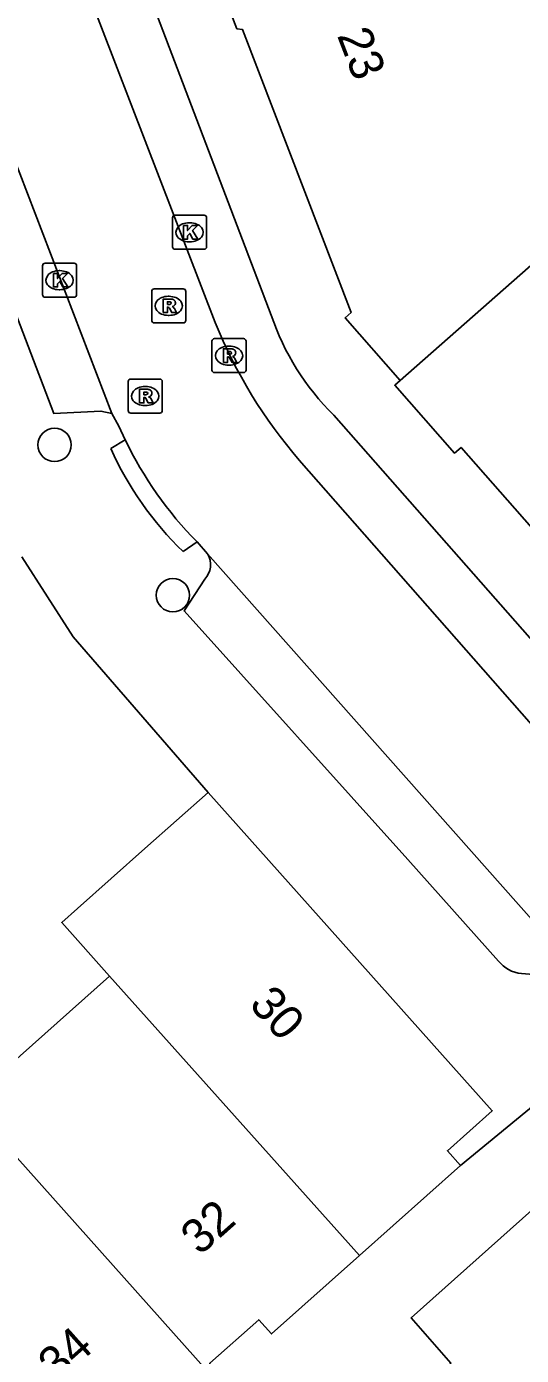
# Model space of a CAD drawing. Extents: x 159961 to 160856, y 382704 to 383353.
# Drawn here: x 160483.81 to 160498.33, y 383016.99 to 383056.02 of the extents above; entities that cross this region are included whole.
import ezdxf

# ---------------------------------------------------------------- set-up
doc = ezdxf.new("R2010")
doc.units = 0
for name, color, linetype in [('IMGEO_Boom', 7, 'Continuous'), ('IMGEO_Kolk', 7, 'Continuous'), ('IMGEO_Pand', 7, 'Continuous'), ('IMGEO_Pand_nummerreeks', 7, 'Continuous'), ('IMGEO_Rijbaan_lokaal_open', 7, 'Continuous'), ('IMGEO_Rioolput', 7, 'Continuous'), ('IMGEO_Voetpad_open', 7, 'Continuous')]:
    doc.layers.add(name, color=color, linetype=linetype)

msp = doc.modelspace()

# ---------------------------------------------------------------- linework, layer by layer
at = {"layer": 'IMGEO_Boom'}
for centre in [(160484.634, 383043.731), (160488.107, 383039.316)]:
    msp.add_circle(centre, 0.489, dxfattribs=at)
at = {"layer": 'IMGEO_Kolk'}
for p, q in [((160488.093, 383049.552), (160488.093, 383050.404)), ((160488.168, 383050.478), (160489.02, 383050.478)), ((160489.094, 383050.404), (160489.094, 383049.552)), ((160488.581, 383050.258), (160488.606, 383050.258)), ((160488.604, 383049.698), (160488.579, 383049.698)), ((160489.02, 383049.478), (160488.168, 383049.478)), ((160484.279, 383048.144), (160484.279, 383048.996)), ((160484.354, 383049.07), (160485.206, 383049.07)), ((160484.767, 383048.85), (160484.792, 383048.85)), ((160485.28, 383048.996), (160485.28, 383048.144)), ((160485.206, 383048.07), (160484.354, 383048.07)), ((160484.79, 383048.29), (160484.765, 383048.29))]:
    msp.add_line(p, q, dxfattribs=at)
for points in [[(160488.093, 383049.552), (160488.093, 383050.404)], [(160488.168, 383050.478), (160489.02, 383050.478)], [(160489.094, 383050.404), (160489.094, 383049.552)], [(160488.414, 383050.178), (160488.537, 383050.178), (160488.537, 383050.027), (160488.667, 383050.178), (160488.831, 383050.178), (160488.685, 383050.027), (160488.838, 383049.778), (160488.686, 383049.778), (160488.601, 383049.942), (160488.537, 383049.875), (160488.537, 383049.778), (160488.414, 383049.778), (160488.414, 383050.178)], [(160489.02, 383049.478), (160488.168, 383049.478)], [(160484.279, 383048.144), (160484.279, 383048.996)], [(160484.354, 383049.07), (160485.206, 383049.07)], [(160484.6, 383048.77), (160484.723, 383048.77), (160484.723, 383048.619), (160484.853, 383048.77), (160485.017, 383048.77), (160484.871, 383048.619), (160485.024, 383048.37), (160484.872, 383048.37), (160484.787, 383048.534), (160484.723, 383048.467), (160484.723, 383048.37), (160484.6, 383048.37), (160484.6, 383048.77)], [(160485.28, 383048.996), (160485.28, 383048.144)], [(160485.206, 383048.07), (160484.354, 383048.07)]]:
    msp.add_lwpolyline(points, dxfattribs=at)
for centre, start, end in [((160488.17, 383050.402), 91.552, 178.448), ((160488.17, 383050.402), 91.552, 178.448), ((160489.018, 383050.402), 1.552, 88.448), ((160489.018, 383050.402), 1.552, 88.448), ((160488.17, 383049.554), 181.552, 268.448), ((160488.17, 383049.554), 181.552, 268.448), ((160489.018, 383049.554), 271.552, 358.448), ((160489.018, 383049.554), 271.552, 358.448), ((160484.356, 383048.994), 91.552, 178.448), ((160484.356, 383048.994), 91.552, 178.448), ((160485.204, 383048.994), 1.552, 88.448), ((160485.204, 383048.994), 1.552, 88.448), ((160484.356, 383048.146), 181.552, 268.448), ((160484.356, 383048.146), 181.552, 268.448), ((160485.204, 383048.146), 271.552, 358.448), ((160485.204, 383048.146), 271.552, 358.448)]:
    msp.add_arc(centre, 0.0765, start, end, dxfattribs=at)
for centre, major_axis, ratio, start_param, end_param in [((160488.58, 383049.978), (-0.387, 0.002), 0.722429, 4.712389, 7.853982), ((160488.605, 383049.978), (-0.39, 0.002), 0.717154, 1.570796, 4.712389), ((160484.766, 383048.57), (-0.387, 0.002), 0.722429, 4.712389, 7.853982), ((160484.791, 383048.57), (-0.39, 0.002), 0.717154, 1.570796, 4.712389)]:
    msp.add_ellipse(centre, major_axis=major_axis, ratio=ratio, start_param=start_param, end_param=end_param, dxfattribs=at)
at = {"layer": 'IMGEO_Pand'}
for points in [[(160494.772, 383045.622), (160493.157, 383047.463), (160493.334, 383047.616), (160490.149, 383055.929), (160489.984, 383055.956), (160488.238, 383060.513), (160488.377, 383060.566), (160487.54, 383062.75), (160487.344, 383062.675), (160486.731, 383064.243)], [(160494.772, 383045.622), (160500, 383050.23), (160501.189, 383051.278), (160501.699, 383050.7), (160505.96, 383054.457)], [(160500.55, 383038.771), (160500.28, 383039.078), (160500.455, 383039.226), (160500, 383039.744), (160496.56, 383043.66), (160496.366, 383043.49), (160494.616, 383045.484), (160494.772, 383045.622)], [(160486.246, 383028.13), (160484.846, 383029.698), (160485.311, 383030.113), (160487.286, 383031.874), (160489.136, 383033.524)], [(160489.136, 383033.524), (160497.475, 383024.171), (160496.158, 383022.996), (160496.543, 383022.564)], [(160482.075, 383024.411), (160486.246, 383028.13)], [(160486.246, 383028.13), (160493.577, 383019.919)], [(160489.174, 383016.46), (160482.075, 383024.411)], [(160493.577, 383019.919), (160496.543, 383022.564)], [(160493.577, 383019.919), (160490.995, 383017.618), (160490.622, 383018.036), (160489.191, 383016.76), (160489.174, 383016.46)]]:
    msp.add_lwpolyline(points, dxfattribs=at)
at = {"layer": 'IMGEO_Rijbaan_lokaal_open'}
for points in [[(160489.35, 383047.33), (160483.958, 383061.336)], [(160486.314, 383044.65), (160480.452, 383059.937)], [(160486.707, 383043.878), (160486.52, 383044.285), (160486.314, 383044.65)], [(160503.746, 383030.245), (160503.457, 383030.012), (160491.815, 383043.282)], [(160489.125, 383040.531), (160488.815, 383040.881)], [(160489.125, 383040.531), (160500.697, 383027.462), (160500.334, 383027.185)]]:
    msp.add_lwpolyline(points, dxfattribs=at)
for centre, radius, start, end in [((160502.589, 383052.617), 14.256, 201.7703, 220.9078), ((160496.744, 383048.698), 11.134, 205.6505, 224.5923)]:
    msp.add_arc(centre, radius, start, end, dxfattribs=at)
at = {"layer": 'IMGEO_Rioolput'}
for p, q in [((160487.483, 383047.39), (160487.483, 383048.242)), ((160487.558, 383048.316), (160488.41, 383048.316)), ((160487.971, 383048.096), (160487.996, 383048.096)), ((160488.484, 383048.242), (160488.484, 383047.39)), ((160488.41, 383047.316), (160487.558, 383047.316)), ((160487.994, 383047.536), (160487.969, 383047.536)), ((160489.251, 383045.928), (160489.251, 383046.78)), ((160489.326, 383046.854), (160490.178, 383046.854)), ((160490.252, 383046.78), (160490.252, 383045.928)), ((160489.739, 383046.634), (160489.764, 383046.634)), ((160489.762, 383046.074), (160489.737, 383046.074)), ((160486.868, 383045.666), (160487.72, 383045.666)), ((160490.178, 383045.854), (160489.326, 383045.854)), ((160486.793, 383044.74), (160486.793, 383045.592)), ((160487.281, 383045.446), (160487.306, 383045.446)), ((160487.794, 383045.592), (160487.794, 383044.74)), ((160487.304, 383044.886), (160487.279, 383044.886)), ((160487.72, 383044.666), (160486.868, 383044.666))]:
    msp.add_line(p, q, dxfattribs=at)
for points in [[(160487.483, 383047.39), (160487.483, 383048.242)], [(160487.558, 383048.316), (160488.41, 383048.316)], [(160488.072, 383048.014), (160487.82, 383048.016), (160487.82, 383047.616)], [(160488.484, 383048.242), (160488.484, 383047.39)], [(160487.82, 383047.616), (160487.944, 383047.616), (160487.944, 383047.778), (160487.955, 383047.778)], [(160487.998, 383047.935), (160487.944, 383047.935), (160487.944, 383047.854)], [(160487.944, 383047.854), (160487.996, 383047.854)], [(160488.002, 383047.749), (160488.073, 383047.616), (160488.213, 383047.616), (160488.148, 383047.742)], [(160488.41, 383047.316), (160487.558, 383047.316)], [(160489.251, 383045.928), (160489.251, 383046.78)], [(160489.326, 383046.854), (160490.178, 383046.854)], [(160490.252, 383046.78), (160490.252, 383045.928)], [(160489.84, 383046.552), (160489.588, 383046.554), (160489.588, 383046.154)], [(160489.766, 383046.473), (160489.712, 383046.473), (160489.712, 383046.392)], [(160489.712, 383046.392), (160489.764, 383046.392)], [(160489.588, 383046.154), (160489.712, 383046.154), (160489.712, 383046.316), (160489.723, 383046.316)], [(160489.77, 383046.287), (160489.841, 383046.154), (160489.981, 383046.154), (160489.916, 383046.28)], [(160486.868, 383045.666), (160487.72, 383045.666)], [(160490.178, 383045.854), (160489.326, 383045.854)], [(160486.793, 383044.74), (160486.793, 383045.592)], [(160487.382, 383045.364), (160487.13, 383045.366), (160487.13, 383044.966)], [(160487.308, 383045.285), (160487.254, 383045.285), (160487.254, 383045.204)], [(160487.794, 383045.592), (160487.794, 383044.74)], [(160487.13, 383044.966), (160487.254, 383044.966), (160487.254, 383045.128), (160487.265, 383045.128)], [(160487.254, 383045.204), (160487.306, 383045.204)], [(160487.312, 383045.099), (160487.383, 383044.966), (160487.523, 383044.966), (160487.458, 383045.092)], [(160487.72, 383044.666), (160486.868, 383044.666)]]:
    msp.add_lwpolyline(points, dxfattribs=at)
for centre, radius, start, end in [((160487.56, 383048.24), 0.0765, 91.552, 178.448), ((160487.56, 383048.24), 0.0765, 91.552, 178.448), ((160488.071, 383047.904), 0.109, 350.3612, 89.416), ((160488.408, 383048.24), 0.0765, 1.552, 88.448), ((160488.408, 383048.24), 0.0765, 1.552, 88.448), ((160487.954, 383047.725), 0.0533, 26.0293, 88.6989), ((160487.98, 383048.043), 0.19, 274.7715, 282.9687), ((160488.004, 383047.839), 0.0964, 77.0061, 93.1865), ((160488.018, 383047.896), 0.0378, 276.6634, 79.6772), ((160488.069, 383047.904), 0.112, 277.5842, 350.9817), ((160488.053, 383047.689), 0.108, 29.5134, 73.7905), ((160487.56, 383047.392), 0.0765, 181.552, 268.448), ((160487.56, 383047.392), 0.0765, 181.552, 268.448), ((160488.408, 383047.392), 0.0765, 271.552, 358.448), ((160488.408, 383047.392), 0.0765, 271.552, 358.448), ((160489.328, 383046.778), 0.0765, 91.552, 178.448), ((160489.328, 383046.778), 0.0765, 91.552, 178.448), ((160490.176, 383046.778), 0.0765, 1.552, 88.448), ((160490.176, 383046.778), 0.0765, 1.552, 88.448), ((160489.748, 383046.581), 0.19, 274.7715, 282.9687), ((160489.772, 383046.377), 0.0964, 77.0061, 93.1865), ((160489.786, 383046.434), 0.0378, 276.6634, 79.6772), ((160489.839, 383046.442), 0.109, 350.3612, 89.416), ((160489.837, 383046.442), 0.112, 277.5842, 350.9817), ((160489.722, 383046.263), 0.0533, 26.0293, 88.6989), ((160489.821, 383046.227), 0.108, 29.5134, 73.7905), ((160486.87, 383045.59), 0.0765, 91.552, 178.448), ((160486.87, 383045.59), 0.0765, 91.552, 178.448), ((160487.718, 383045.59), 0.0765, 1.552, 88.448), ((160487.718, 383045.59), 0.0765, 1.552, 88.448), ((160489.328, 383045.93), 0.0765, 181.552, 268.448), ((160489.328, 383045.93), 0.0765, 181.552, 268.448), ((160490.176, 383045.93), 0.0765, 271.552, 358.448), ((160490.176, 383045.93), 0.0765, 271.552, 358.448), ((160487.314, 383045.189), 0.0964, 77.0061, 93.1865), ((160487.328, 383045.246), 0.0378, 276.6634, 79.6772), ((160487.381, 383045.254), 0.109, 350.3612, 89.416), ((160487.379, 383045.254), 0.112, 277.5842, 350.9817), ((160487.264, 383045.075), 0.0533, 26.0293, 88.6989), ((160487.29, 383045.393), 0.19, 274.7715, 282.9687), ((160487.363, 383045.039), 0.108, 29.5134, 73.7905), ((160486.87, 383044.742), 0.0765, 181.552, 268.448), ((160486.87, 383044.742), 0.0765, 181.552, 268.448), ((160487.718, 383044.742), 0.0765, 271.552, 358.448), ((160487.718, 383044.742), 0.0765, 271.552, 358.448)]:
    msp.add_arc(centre, radius, start, end, dxfattribs=at)
for centre, major_axis, ratio, start_param, end_param in [((160487.97, 383047.816), (-0.387, 0.002), 0.722429, 4.712389, 7.853982), ((160487.995, 383047.816), (-0.39, 0.002), 0.717154, 1.570796, 4.712389), ((160489.738, 383046.354), (-0.387, 0.002), 0.722429, 4.712389, 7.853982), ((160489.763, 383046.354), (-0.39, 0.002), 0.717154, 1.570796, 4.712389), ((160487.28, 383045.166), (-0.387, 0.002), 0.722429, 4.712389, 7.853982), ((160487.305, 383045.166), (-0.39, 0.002), 0.717154, 1.570796, 4.712389)]:
    msp.add_ellipse(centre, major_axis=major_axis, ratio=ratio, start_param=start_param, end_param=end_param, dxfattribs=at)
at = {"layer": 'IMGEO_Voetpad_open'}
for points in [[(160486.314, 383044.65), (160485.994, 383044.724), (160484.611, 383044.657), (160454.903, 383122.684)], [(160485.898, 383060.96), (160490.989, 383047.546)], [(160492.825, 383044.606), (160499.804, 383036.677), (160500, 383036.453), (160502.796, 383033.253)], [(160486.28, 383043.627), (160486.707, 383043.878)], [(160488.815, 383040.881), (160488.405, 383040.596)], [(160483.669, 383040.448), (160485.177, 383038.098), (160489.136, 383033.524)], [(160497.656, 383028.57), (160495.002, 383031.555), (160488.436, 383038.855), (160489.043, 383039.783)], [(160499.04, 383028.147), (160498.33, 383028.201)], [(160496.543, 383022.564), (160501.09, 383026.309)], [(160501.564, 383023.866), (160500, 383022.47), (160495.094, 383018.089), (160496.262, 383016.757), (160488.868, 383010.134)]]:
    msp.add_lwpolyline(points, dxfattribs=at)
for centre, radius, start, end in [((160498.11, 383049.949), 7.515, 198.6513, 225.3174), ((160495.314, 383047.7), 9.91, 204.2696, 225.7981), ((160488.566, 383040.214), 0.642, 317.896, 29.5918), ((160498.435, 383029.193), 0.997, 218.6415, 263.9591)]:
    msp.add_arc(centre, radius, start, end, dxfattribs=at)

# ---------------------------------------------------------------- texts
at = {"layer": 'IMGEO_Pand_nummerreeks'}
for s, rotation, p in [('23', 290.9471, (160492.914, 383055.763)), ('30', 311.7226, (160490.311, 383027.277)), ('32', 41.7213, (160488.898, 383019.9)), ('34', 41.7213, (160484.713, 383016.168))]:
    msp.add_text(s, height=1, rotation=rotation, dxfattribs=at).set_placement(p)

doc.saveas('drawing.dxf')
